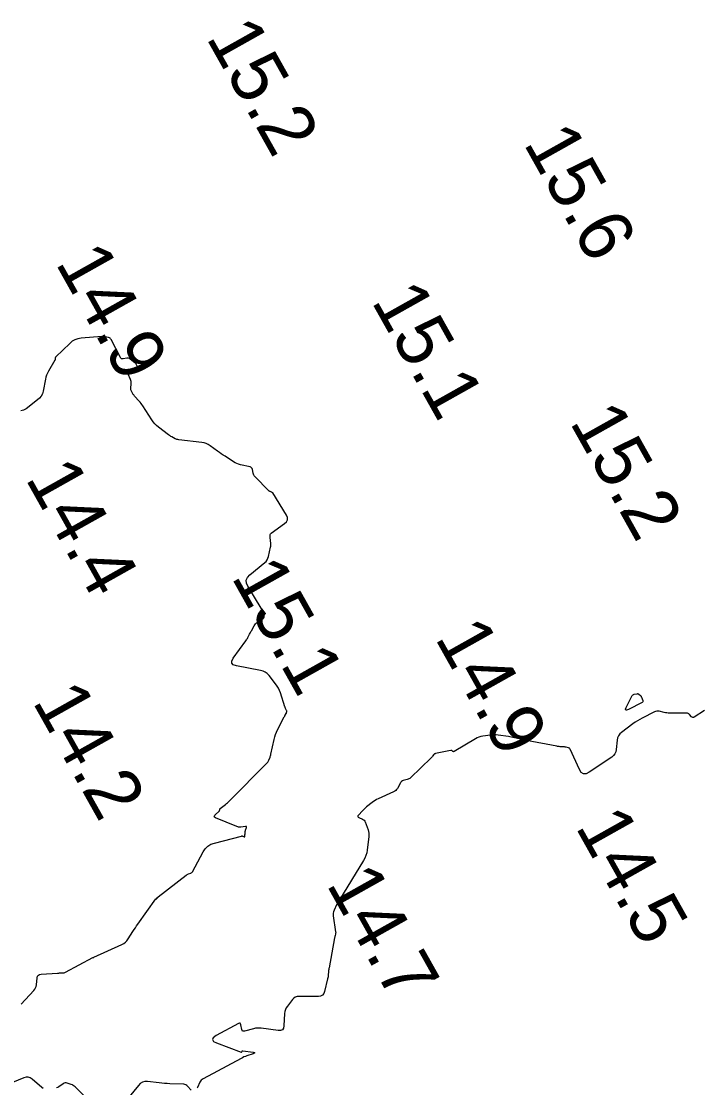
# Model space of a CAD drawing. Extents: x 1023796 to 1112670, y 656573 to 837340.
# Drawn here: x 1109025.4 to 1109088.6, y 682551 to 682649.9 of the extents above; entities that cross this region are included whole.
import ezdxf

# ---------------------------------------------------------------- set-up
doc = ezdxf.new("R2010")
doc.units = 0
doc.layers.add('V-CHAN-CONT-15FT', color=7, linetype='Continuous')
doc.layers.add('V-TOPO-SOUN', color=7, linetype='Continuous')

msp = doc.modelspace()

# ---------------------------------------------------------------- linework, layer by layer
at = {"layer": 'V-CHAN-CONT-15FT'}
for points in [[(1109025.334, 682558.784), (1109026.509, 682560.048), (1109026.606, 682560.17), (1109026.68, 682560.303), (1109026.732, 682560.446), (1109026.761, 682560.599), (1109026.83, 682561.235), (1109026.865, 682561.375), (1109026.936, 682561.479), (1109027.042, 682561.545), (1109027.183, 682561.574), (1109028.698, 682561.674), (1109028.762, 682561.678), (1109028.825, 682561.682), (1109028.889, 682561.684), (1109028.953, 682561.686), (1109029.208, 682561.694), (1109029.271, 682561.699), (1109029.332, 682561.712), (1109029.391, 682561.731), (1109029.448, 682561.757), (1109032.001, 682563.119), (1109032.007, 682563.122), (1109032.013, 682563.124), (1109032.02, 682563.126), (1109032.026, 682563.127), (1109032.053, 682563.131), (1109032.06, 682563.133), (1109032.066, 682563.134), (1109032.072, 682563.136), (1109032.079, 682563.139), (1109034.676, 682564.319), (1109034.854, 682564.415), (1109035.013, 682564.534), (1109035.152, 682564.675), (1109035.272, 682564.838), (1109035.712, 682565.536), (1109035.823, 682565.709), (1109035.936, 682565.881), (1109036.052, 682566.052), (1109036.17, 682566.221), (1109037.822, 682568.548), (1109037.828, 682568.555), (1109037.835, 682568.56), (1109037.843, 682568.564), (1109037.852, 682568.565), (1109037.891, 682568.567), (1109037.9, 682568.568), (1109037.908, 682568.571), (1109037.915, 682568.576), (1109037.922, 682568.583), (1109037.995, 682568.675), (1109038.01, 682568.692), (1109038.025, 682568.709), (1109038.042, 682568.724), (1109038.06, 682568.739), (1109040.654, 682570.768), (1109040.7, 682570.801), (1109040.748, 682570.829), (1109040.799, 682570.852), (1109040.852, 682570.871), (1109041.068, 682570.939), (1109041.119, 682570.96), (1109041.162, 682570.99), (1109041.199, 682571.027), (1109041.229, 682571.073), (1109042.208, 682572.909), (1109042.403, 682573.202), (1109042.643, 682573.438), (1109042.929, 682573.616), (1109043.26, 682573.736), (1109045.773, 682574.385), (1109045.805, 682574.391), (1109045.837, 682574.39), (1109045.867, 682574.384), (1109045.897, 682574.371), (1109046.016, 682574.31), (1109046.042, 682574.301), (1109046.062, 682574.304), (1109046.075, 682574.319), (1109046.082, 682574.346), (1109046.095, 682574.479), (1109046.099, 682574.512), (1109046.102, 682574.545), (1109046.104, 682574.579), (1109046.107, 682574.612), (1109046.117, 682574.77), (1109046.12, 682574.807), (1109046.126, 682574.844), (1109046.134, 682574.88), (1109046.145, 682574.916), (1109046.231, 682575.179), (1109046.24, 682575.227), (1109046.23, 682575.259), (1109046.2, 682575.275), (1109046.152, 682575.275), (1109045.699, 682575.215), (1109045.606, 682575.209), (1109045.513, 682575.215), (1109045.422, 682575.233), (1109045.333, 682575.263), (1109043.361, 682576.076), (1109043.285, 682576.12), (1109043.252, 682576.174), (1109043.261, 682576.236), (1109043.312, 682576.307), (1109043.724, 682576.736), (1109043.735, 682576.75), (1109043.744, 682576.764), (1109043.749, 682576.78), (1109043.752, 682576.798), (1109043.759, 682576.869), (1109043.762, 682576.886), (1109043.769, 682576.901), (1109043.778, 682576.915), (1109043.791, 682576.926), (1109044.294, 682577.318), (1109044.382, 682577.388), (1109044.467, 682577.461), (1109044.55, 682577.537), (1109044.63, 682577.615), (1109048.163, 682581.172), (1109048.212, 682581.227), (1109048.254, 682581.286), (1109048.29, 682581.349), (1109048.32, 682581.416), (1109048.424, 682581.692), (1109048.449, 682581.762), (1109048.471, 682581.832), (1109048.49, 682581.904), (1109048.507, 682581.976), (1109048.795, 682583.337), (1109048.853, 682583.569), (1109048.926, 682583.796), (1109049.014, 682584.017), (1109049.117, 682584.233), (1109049.746, 682585.438), (1109049.765, 682585.475), (1109049.785, 682585.511), (1109049.805, 682585.547), (1109049.825, 682585.583), (1109049.925, 682585.755), (1109049.936, 682585.777), (1109049.945, 682585.799), (1109049.951, 682585.821), (1109049.956, 682585.845), (1109049.97, 682585.94), (1109049.972, 682585.963), (1109049.97, 682585.986), (1109049.964, 682586.009), (1109049.956, 682586.031), (1109049.868, 682586.207), (1109049.85, 682586.244), (1109049.834, 682586.281), (1109049.819, 682586.319), (1109049.806, 682586.358), (1109049.383, 682587.652), (1109049.3, 682587.876), (1109049.197, 682588.09), (1109049.077, 682588.295), (1109048.938, 682588.489), (1109048.328, 682589.271), (1109048.166, 682589.446), (1109047.981, 682589.583), (1109047.773, 682589.684), (1109047.543, 682589.746), (1109045.303, 682590.157), (1109045.018, 682590.251), (1109044.875, 682590.401), (1109044.874, 682590.609), (1109045.014, 682590.874), (1109046.179, 682592.492), (1109046.229, 682592.565), (1109046.277, 682592.639), (1109046.323, 682592.716), (1109046.366, 682592.793), (1109046.532, 682593.108), (1109046.573, 682593.187), (1109046.615, 682593.265), (1109046.657, 682593.343), (1109046.7, 682593.422), (1109046.949, 682593.88), (1109047.01, 682593.977), (1109047.081, 682594.065), (1109047.163, 682594.142), (1109047.256, 682594.21), (1109047.792, 682594.553), (1109047.856, 682594.607), (1109047.893, 682594.671), (1109047.903, 682594.744), (1109047.886, 682594.826), (1109047.762, 682595.174), (1109047.729, 682595.26), (1109047.691, 682595.343), (1109047.65, 682595.425), (1109047.604, 682595.505), (1109046.356, 682597.543), (1109046.227, 682597.838), (1109046.214, 682598.113), (1109046.318, 682598.368), (1109046.537, 682598.603), (1109047.928, 682599.733), (1109048.052, 682599.852), (1109048.152, 682599.986), (1109048.228, 682600.135), (1109048.279, 682600.3), (1109048.477, 682601.184), (1109048.49, 682601.259), (1109048.498, 682601.333), (1109048.499, 682601.408), (1109048.494, 682601.484), (1109048.458, 682601.821), (1109048.453, 682601.879), (1109048.449, 682601.937), (1109048.446, 682601.996), (1109048.445, 682602.054), (1109048.444, 682602.289), (1109048.449, 682602.344), (1109048.467, 682602.394), (1109048.497, 682602.437), (1109048.539, 682602.474), (1109049.777, 682603.355), (1109049.954, 682603.523), (1109050.039, 682603.709), (1109050.033, 682603.913), (1109049.936, 682604.137), (1109048.669, 682606.194), (1109048.649, 682606.222), (1109048.625, 682606.245), (1109048.597, 682606.264), (1109048.566, 682606.278), (1109048.433, 682606.325), (1109048.4, 682606.338), (1109048.37, 682606.355), (1109048.342, 682606.375), (1109048.317, 682606.399), (1109047.023, 682607.711), (1109046.964, 682607.779), (1109046.917, 682607.854), (1109046.881, 682607.935), (1109046.857, 682608.023), (1109046.784, 682608.384), (1109046.757, 682608.465), (1109046.711, 682608.53), (1109046.648, 682608.576), (1109046.568, 682608.606), (1109045.684, 682608.812), (1109045.51, 682608.86), (1109045.342, 682608.923), (1109045.181, 682609.001), (1109045.025, 682609.093), (1109044.253, 682609.596), (1109044.076, 682609.713), (1109043.9, 682609.832), (1109043.726, 682609.954), (1109043.552, 682610.077), (1109042.863, 682610.576), (1109042.686, 682610.688), (1109042.499, 682610.775), (1109042.303, 682610.837), (1109042.097, 682610.874), (1109039.952, 682611.125), (1109039.866, 682611.139), (1109039.782, 682611.161), (1109039.701, 682611.191), (1109039.622, 682611.229), (1109039.313, 682611.397), (1109039.236, 682611.441), (1109039.162, 682611.487), (1109039.089, 682611.536), (1109039.018, 682611.587), (1109038.067, 682612.304), (1109037.892, 682612.448), (1109037.733, 682612.606), (1109037.588, 682612.778), (1109037.458, 682612.963), (1109036.613, 682614.29), (1109036.541, 682614.398), (1109036.464, 682614.503), (1109036.383, 682614.605), (1109036.298, 682614.703), (1109035.862, 682615.182), (1109035.818, 682615.233), (1109035.777, 682615.286), (1109035.74, 682615.341), (1109035.705, 682615.398), (1109035.573, 682615.632), (1109035.545, 682615.692), (1109035.525, 682615.753), (1109035.516, 682615.817), (1109035.515, 682615.883), (1109035.541, 682616.334), (1109035.541, 682616.43), (1109035.531, 682616.525), (1109035.51, 682616.618), (1109035.479, 682616.71), (1109035.276, 682617.205), (1109035.258, 682617.278), (1109035.27, 682617.334), (1109035.311, 682617.374), (1109035.382, 682617.397), (1109035.793, 682617.469), (1109035.843, 682617.483), (1109035.888, 682617.506), (1109035.926, 682617.538), (1109035.959, 682617.579), (1109036.082, 682617.77), (1109036.103, 682617.813), (1109036.113, 682617.856), (1109036.11, 682617.9), (1109036.096, 682617.945), (1109036.017, 682618.127), (1109035.995, 682618.171), (1109035.968, 682618.211), (1109035.935, 682618.246), (1109035.898, 682618.278), (1109035.45, 682618.613), (1109035.378, 682618.657), (1109035.302, 682618.684), (1109035.222, 682618.694), (1109035.137, 682618.687), (1109034.792, 682618.627), (1109034.712, 682618.624), (1109034.643, 682618.644), (1109034.586, 682618.687), (1109034.54, 682618.753), (1109033.681, 682620.439), (1109033.64, 682620.503), (1109033.588, 682620.554), (1109033.526, 682620.592), (1109033.454, 682620.616), (1109033.143, 682620.687), (1109033.065, 682620.702), (1109032.987, 682620.711), (1109032.908, 682620.713), (1109032.829, 682620.71), (1109030.905, 682620.553), (1109030.606, 682620.503), (1109030.328, 682620.406), (1109030.073, 682620.261), (1109029.839, 682620.068), (1109028.54, 682618.807), (1109028.522, 682618.786), (1109028.51, 682618.764), (1109028.503, 682618.739), (1109028.501, 682618.712), (1109028.504, 682618.601), (1109028.503, 682618.574), (1109028.498, 682618.548), (1109028.49, 682618.523), (1109028.477, 682618.499), (1109027.87, 682617.497), (1109027.773, 682617.319), (1109027.692, 682617.134), (1109027.628, 682616.943), (1109027.582, 682616.745), (1109027.37, 682615.632), (1109027.303, 682615.392), (1109027.196, 682615.176), (1109027.05, 682614.985), (1109026.864, 682614.818), (1109025.797, 682614.012), (1109025.549, 682613.871), (1109025.299, 682613.82)], [(1109088.725, 682586.021), (1109087.757, 682585.418), (1109087.695, 682585.39), (1109087.636, 682585.386), (1109087.58, 682585.405), (1109087.527, 682585.448), (1109087.321, 682585.666), (1109087.267, 682585.714), (1109087.207, 682585.748), (1109087.141, 682585.769), (1109087.068, 682585.776), (1109085.464, 682585.78), (1109085.345, 682585.784), (1109085.226, 682585.794), (1109085.109, 682585.812), (1109084.992, 682585.836), (1109084.526, 682585.948), (1109084.411, 682585.966), (1109084.298, 682585.963), (1109084.187, 682585.939), (1109084.08, 682585.895), (1109082.943, 682585.314), (1109082.721, 682585.195), (1109082.504, 682585.067), (1109082.292, 682584.93), (1109082.086, 682584.785), (1109081.013, 682583.998), (1109080.853, 682583.854), (1109080.733, 682583.688), (1109080.653, 682583.499), (1109080.613, 682583.288), (1109080.533, 682582.397), (1109080.492, 682582.187), (1109080.41, 682582.001), (1109080.287, 682581.84), (1109080.122, 682581.703), (1109078.031, 682580.295), (1109077.748, 682580.159), (1109077.503, 682580.156), (1109077.295, 682580.286), (1109077.125, 682580.551), (1109076.265, 682582.435), (1109076.238, 682582.481), (1109076.203, 682582.518), (1109076.16, 682582.546), (1109076.11, 682582.564), (1109075.892, 682582.617), (1109075.837, 682582.63), (1109075.782, 682582.639), (1109075.727, 682582.646), (1109075.671, 682582.65), (1109075.319, 682582.669), (1109075.242, 682582.674), (1109075.165, 682582.682), (1109075.088, 682582.693), (1109075.012, 682582.706), (1109072.205, 682583.231), (1109072.064, 682583.259), (1109071.924, 682583.288), (1109071.784, 682583.319), (1109071.645, 682583.352), (1109071.088, 682583.488), (1109070.949, 682583.52), (1109070.809, 682583.549), (1109070.668, 682583.575), (1109070.527, 682583.599), (1109069.569, 682583.745), (1109069.391, 682583.765), (1109069.213, 682583.772), (1109069.035, 682583.765), (1109068.858, 682583.745), (1109068.147, 682583.635), (1109067.972, 682583.6), (1109067.803, 682583.548), (1109067.64, 682583.481), (1109067.482, 682583.397), (1109065.509, 682582.225), (1109065.479, 682582.211), (1109065.449, 682582.207), (1109065.42, 682582.213), (1109065.391, 682582.227), (1109065.275, 682582.304), (1109065.245, 682582.32), (1109065.215, 682582.33), (1109065.183, 682582.332), (1109065.149, 682582.328), (1109063.769, 682582.029), (1109063.724, 682582.015), (1109063.683, 682581.994), (1109063.647, 682581.966), (1109063.616, 682581.931), (1109063.499, 682581.777), (1109063.469, 682581.739), (1109063.438, 682581.702), (1109063.405, 682581.666), (1109063.371, 682581.632), (1109061.446, 682579.792), (1109061.376, 682579.734), (1109061.301, 682579.685), (1109061.221, 682579.646), (1109061.134, 682579.617), (1109060.778, 682579.522), (1109060.695, 682579.492), (1109060.622, 682579.446), (1109060.561, 682579.387), (1109060.512, 682579.313), (1109060.231, 682578.799), (1109060.163, 682578.694), (1109060.08, 682578.604), (1109059.984, 682578.529), (1109059.874, 682578.469), (1109058.444, 682577.829), (1109058.302, 682577.761), (1109058.166, 682577.684), (1109058.034, 682577.6), (1109057.908, 682577.507), (1109057.361, 682577.08), (1109057.264, 682577), (1109057.17, 682576.916), (1109057.081, 682576.828), (1109056.995, 682576.736), (1109056.617, 682576.308), (1109056.573, 682576.242), (1109056.567, 682576.185), (1109056.597, 682576.135), (1109056.664, 682576.094), (1109057.006, 682575.945), (1109057.085, 682575.901), (1109057.15, 682575.845), (1109057.202, 682575.776), (1109057.241, 682575.695), (1109057.513, 682574.954), (1109057.559, 682574.8), (1109057.587, 682574.644), (1109057.596, 682574.486), (1109057.586, 682574.326), (1109057.437, 682573.078), (1109057.392, 682572.821), (1109057.321, 682572.573), (1109057.222, 682572.335), (1109057.098, 682572.106), (1109054.864, 682568.481), (1109054.792, 682568.362), (1109054.724, 682568.242), (1109054.659, 682568.119), (1109054.597, 682567.995), (1109054.356, 682567.496), (1109054.306, 682567.369), (1109054.276, 682567.24), (1109054.266, 682567.107), (1109054.277, 682566.972), (1109054.506, 682565.486), (1109054.511, 682565.44), (1109054.511, 682565.395), (1109054.506, 682565.351), (1109054.497, 682565.306), (1109054.451, 682565.129), (1109054.44, 682565.084), (1109054.43, 682565.04), (1109054.421, 682564.995), (1109054.412, 682564.95), (1109053.895, 682562.177), (1109053.88, 682562.091), (1109053.867, 682562.005), (1109053.857, 682561.919), (1109053.849, 682561.832), (1109053.821, 682561.485), (1109053.812, 682561.398), (1109053.8, 682561.313), (1109053.785, 682561.227), (1109053.766, 682561.142), (1109053.479, 682559.968), (1109053.403, 682559.772), (1109053.282, 682559.632), (1109053.118, 682559.547), (1109052.909, 682559.518), (1109051.104, 682559.512), (1109050.924, 682559.493), (1109050.762, 682559.436), (1109050.618, 682559.343), (1109050.493, 682559.212), (1109050.029, 682558.613), (1109049.926, 682558.459), (1109049.85, 682558.295), (1109049.8, 682558.12), (1109049.776, 682557.936), (1109049.712, 682556.779), (1109049.668, 682556.559), (1109049.565, 682556.413), (1109049.401, 682556.34), (1109049.177, 682556.34), (1109047.61, 682556.564), (1109047.43, 682556.58), (1109047.251, 682556.578), (1109047.073, 682556.558), (1109046.897, 682556.518), (1109046.056, 682556.286), (1109045.959, 682556.274), (1109045.884, 682556.296), (1109045.832, 682556.354), (1109045.801, 682556.447), (1109045.724, 682556.889), (1109045.694, 682556.979), (1109045.645, 682557.028), (1109045.577, 682557.036), (1109045.488, 682557.002), (1109043.422, 682555.873), (1109043.154, 682555.683), (1109043.073, 682555.507), (1109043.179, 682555.344), (1109043.472, 682555.195), (1109045.75, 682554.354), (1109045.767, 682554.351), (1109045.782, 682554.353), (1109045.793, 682554.362), (1109045.802, 682554.377), (1109045.832, 682554.449), (1109045.841, 682554.464), (1109045.853, 682554.475), (1109045.868, 682554.48), (1109045.886, 682554.479), (1109046.846, 682554.342), (1109046.959, 682554.317), (1109046.999, 682554.285), (1109046.966, 682554.246), (1109046.859, 682554.201), (1109046.285, 682554.004), (1109046.143, 682553.952), (1109046.003, 682553.894), (1109045.866, 682553.831), (1109045.731, 682553.762), (1109042.223, 682551.881), (1109042.128, 682551.82), (1109042.047, 682551.748), (1109041.978, 682551.662), (1109041.923, 682551.565), (1109041.684, 682551.054), (1109041.654, 682551.001)], [(1109027.369, 682550.973), (1109027.254, 682551.055), (1109026.354, 682551.842), (1109026.176, 682551.964), (1109025.987, 682552.024), (1109025.789, 682552.024), (1109025.582, 682551.963), (1109024.544, 682551.515)], [(1109041.106, 682550.807), (1109040.771, 682551.193), (1109040.697, 682551.264), (1109040.613, 682551.316), (1109040.521, 682551.349), (1109040.42, 682551.362), (1109039.127, 682551.417), (1109038.876, 682551.43), (1109038.626, 682551.447), (1109038.376, 682551.469), (1109038.127, 682551.495), (1109037.06, 682551.615), (1109036.811, 682551.615), (1109036.586, 682551.557), (1109036.385, 682551.44), (1109036.208, 682551.265), (1109035.066, 682549.852)], [(1109031.287, 682550.198), (1109030.335, 682551.133), (1109030.258, 682551.201), (1109030.176, 682551.258), (1109030.087, 682551.306), (1109029.992, 682551.343), (1109029.6, 682551.473), (1109029.504, 682551.494), (1109029.411, 682551.492), (1109029.321, 682551.467), (1109029.235, 682551.419), (1109028.833, 682551.137), (1109028.735, 682551.077), (1109028.632, 682551.03)]]:
    msp.add_lwpolyline(points, dxfattribs=at)
msp.add_lwpolyline([(1109082.094, 682587.492), (1109082.142, 682587.519), (1109082.197, 682587.535), (1109082.461, 682587.583), (1109082.506, 682587.587), (1109082.55, 682587.58), (1109082.59, 682587.564), (1109082.628, 682587.537), (1109082.773, 682587.412), (1109082.807, 682587.38), (1109082.836, 682587.343), (1109082.861, 682587.304), (1109082.881, 682587.261), (1109083.005, 682586.951), (1109083.021, 682586.889), (1109083.013, 682586.836), (1109082.984, 682586.79), (1109082.931, 682586.753), (1109081.662, 682586.105), (1109081.498, 682586.04), (1109081.411, 682586.051), (1109081.399, 682586.139), (1109081.463, 682586.302), (1109082.023, 682587.406), (1109082.055, 682587.455)], close=True, dxfattribs=at)

# ---------------------------------------------------------------- texts
at = {"layer": 'V-TOPO-SOUN'}
for s, p in [('15.2 ', (1109042.442, 682648.443)), ('15.6 ', (1109071.875, 682638.635)), ('14.9 ', (1109028.462, 682627.543)), ('15.1 ', (1109057.768, 682623.987)), ('15.2 ', (1109076.162, 682612.783)), ('14.4 ', (1109025.672, 682607.563)), ('15.1 ', (1109044.778, 682598.427)), ('14.9 ', (1109063.662, 682592.773)), ('14.2 ', (1109026.332, 682586.863)), ('14.5 ', (1109076.689, 682575.258)), ('14.7 ', (1109053.592, 682569.933))]:
    msp.add_text(s, height=5, rotation=299.30014, dxfattribs=at).set_placement(p)

doc.saveas('drawing.dxf')
